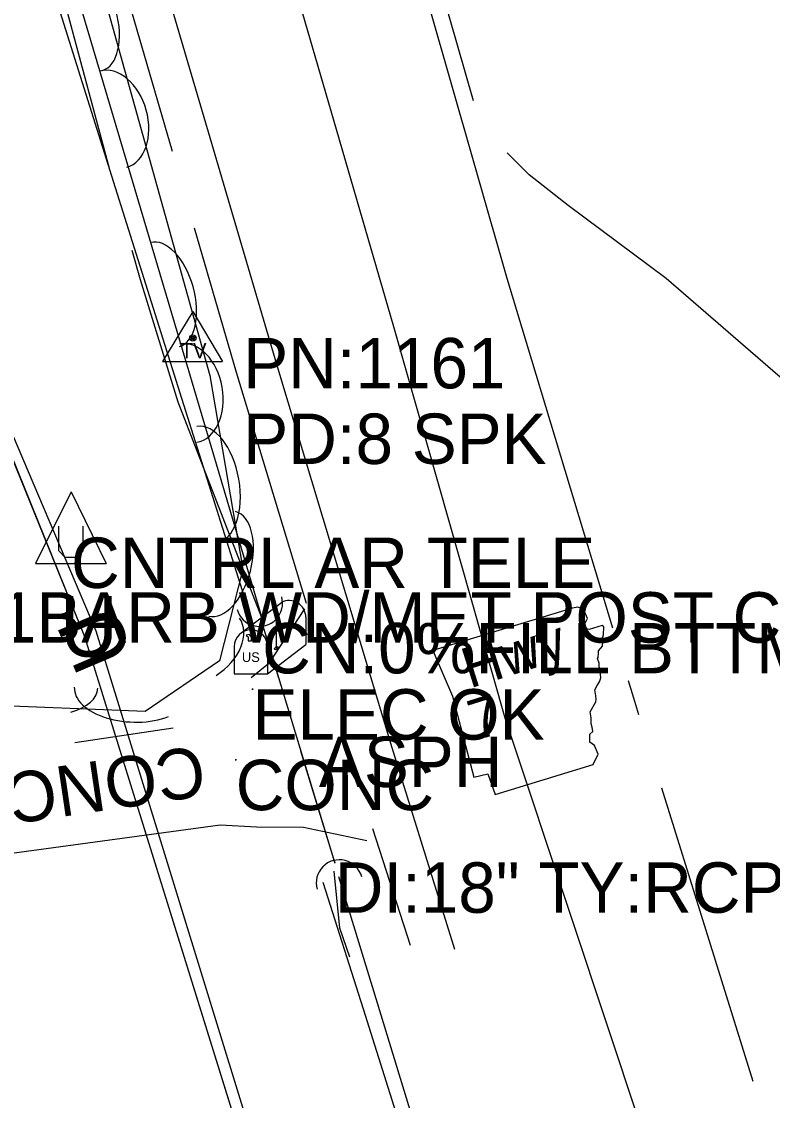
# Model space of a CAD drawing. Extents: x 954793 to 988390, y 1867850 to 1924428.
# Drawn here: x 960863.5 to 960938.1, y 1908205.7 to 1908312.7 of the extents above; entities that cross this region are included whole.
import ezdxf

# ---------------------------------------------------------------- set-up
doc = ezdxf.new("R2010")
doc.units = 0
for name, color, linetype in [('Default', 7, 'Continuous'), ('S_CROSS_DRAIN', 7, 'Continuous'), ('S_DITCHLINE', 7, 'Continuous'), ('S_DRG_PT_SYM', 7, 'Continuous'), ('S_DRIVEWAY', 7, 'Continuous'), ('S_DRIVEWAY_ANNOT', 7, 'Continuous'), ('S_EDGE_PAVEMENT', 7, 'Continuous'), ('S_FIBER_OPTIC_CABLE', 7, 'Continuous'), ('S_GRAVEL_ROAD', 7, 'Continuous'), ('S_HWY_SYMBOLS', 7, 'Continuous'), ('S_MAILBOX', 7, 'Continuous'), ('S_MSC_PT_SYM', 7, 'Continuous'), ('S_PAVEMENT_CROWN', 7, 'Continuous'), ('S_SECONDARY_CTL', 7, 'Continuous'), ('S_SECONDARY_CTL_ANNOT', 7, 'Continuous'), ('S_SHOULDER', 7, 'Continuous'), ('S_SIDE_DRAIN', 7, 'Continuous'), ('S_SIDE_DRAIN_ANNOT', 7, 'Continuous'), ('S_STREAM', 7, 'Continuous'), ('S_SURVEY_TEXT_ANNOT', 7, 'Continuous'), ('S_TREE', 7, 'Continuous'), ('S_UNDERGROUND_CABLE', 7, 'Continuous'), ('S_UTILITY_POLE_ANNOT', 7, 'Continuous'), ('S_UTL_PT_SYM', 7, 'Continuous')]:
    doc.layers.add(name, color=color, linetype=linetype)

msp = doc.modelspace()

# ---------------------------------------------------------------- linework, layer by layer
at = {"layer": 'S_CROSS_DRAIN'}
for centre, start, end in [((960887.14, 1908255.03), 195.5364, 15.8656), ((960895.08, 1908227.28), 15.5364, 195.8656)]:
    msp.add_arc(centre, 2.3, start, end, dxfattribs=at)
at = {"layer": 'S_DITCHLINE'}
for points in [[(960887.32, 1908253.86), (960880.93, 1908275.39), (960874.54, 1908296.92), (960868.15, 1908318.45), (960861.75, 1908339.98), (960857.4, 1908356.82), (960853.05, 1908373.67), (960848.7, 1908390.51), (960844.35, 1908407.36), (960839.66, 1908426.7), (960834.97, 1908446.05), (960830.28, 1908465.39), (960825.59, 1908484.73), (960820.79, 1908504.11), (960815.99, 1908523.48), (960811.19, 1908542.85), (960806.38, 1908562.22)], [(960886.41, 1908253.21), (960879.64, 1908274.72), (960872.87, 1908296.22), (960866.11, 1908317.73), (960859.34, 1908339.24), (960855.61, 1908355.76), (960851.88, 1908372.29), (960848.14, 1908388.81), (960844.41, 1908405.34), (960839.36, 1908425.07), (960834.31, 1908444.81), (960829.25, 1908464.54), (960824.2, 1908484.28), (960819.45, 1908503.76), (960814.7, 1908523.23), (960809.95, 1908542.71), (960805.2, 1908562.19)], [(960909.41, 1908177), (960905.43, 1908189.59), (960901.44, 1908202.17), (960897.46, 1908214.75), (960893.47, 1908227.34)], [(960910.38, 1908177.7), (960906.54, 1908190.25), (960902.7, 1908202.8), (960898.86, 1908215.34), (960895.02, 1908227.89)]]:
    msp.add_lwpolyline(points, dxfattribs=at)
at = {"layer": 'S_DRG_PT_SYM'}
for points in [[(960887.41, 1908253.07), (960887.36, 1908253.05), (960887.41, 1908253.07), (960887.42, 1908253.02), (960887.41, 1908253.07), (960887.45, 1908253.08), (960887.41, 1908253.07), (960887.39, 1908253.12)], [(960887.41, 1908253.07), (960887.36, 1908253.05), (960887.41, 1908253.07), (960887.42, 1908253.02), (960887.41, 1908253.07), (960887.45, 1908253.08), (960887.41, 1908253.07), (960887.39, 1908253.12)], [(960894.62, 1908229.32), (960894.57, 1908229.31), (960894.62, 1908229.32), (960894.63, 1908229.28), (960894.62, 1908229.32), (960894.66, 1908229.34), (960894.62, 1908229.32), (960894.6, 1908229.37)], [(960894.62, 1908229.32), (960894.57, 1908229.31), (960894.62, 1908229.32), (960894.63, 1908229.28), (960894.62, 1908229.32), (960894.66, 1908229.34), (960894.62, 1908229.32), (960894.6, 1908229.37)]]:
    msp.add_lwpolyline(points, close=True, dxfattribs=at)
for points in [[(960887.41, 1908253.07), (960887.41, 1908253.12), (960887.41, 1908253.07), (960887.36, 1908253.07), (960887.41, 1908253.07), (960887.41, 1908253.02), (960887.41, 1908253.07), (960887.46, 1908253.07)], [(960894.62, 1908229.32), (960894.62, 1908229.37), (960894.62, 1908229.32), (960894.57, 1908229.32), (960894.62, 1908229.32), (960894.62, 1908229.27), (960894.62, 1908229.32), (960894.67, 1908229.32)]]:
    msp.add_lwpolyline(points, dxfattribs=at)
at = {"layer": 'S_DRIVEWAY'}
for points in [[(960891.63, 1908254.46), (960888.04, 1908249.01), (960886.32, 1908247.64)], [(960878.58, 1908242.65), (960868.84, 1908241.18)], [(960835.9, 1908227.05), (960844.09, 1908228), (960858.41, 1908229.67), (960870.84, 1908231.37), (960883.26, 1908233.06), (960886.86, 1908232.86), (960891.51, 1908232.83), (960897.8, 1908231.49)]]:
    msp.add_lwpolyline(points, dxfattribs=at)
at = {"layer": 'S_EDGE_PAVEMENT'}
for points in [[(960922.21, 1908252.54), (960918.02, 1908266.43), (960911.74, 1908287.24), (960905.85, 1908307.8), (960899.95, 1908328.37)], [(960906.54, 1908220.67), (960900.33, 1908240.69), (960894.59, 1908259.7), (960888.86, 1908278.72), (960882.58, 1908300.08), (960876.3, 1908321.43)], [(960924.81, 1908243.97), (960924.3, 1908245.62), (960923.78, 1908247.34)], [(960936.15, 1908207.57), (960930.39, 1908226.07), (960927.09, 1908236.67)]]:
    msp.add_lwpolyline(points, dxfattribs=at)
at = {"layer": 'S_FIBER_OPTIC_CABLE'}
for p, q in [((960869.82, 1908251.7), (960854.87, 1908288.42)), ((960891.98, 1908180.4), (960869.82, 1908251.7))]:
    msp.add_line(p, q, dxfattribs=at)
msp.add_lwpolyline([(961081.83, 1907606.88), (961053.28, 1907681.02), (961044.49, 1907703.08), (961020.93, 1907758.22), (961005.92, 1907782.73), (960987.1, 1907843.87), (960969.61, 1907900.06), (960943.98, 1907978.41), (960937.29, 1908004.83), (960935.36, 1908054.81), (960930.43, 1908064.73), (960909.05, 1908124.58), (960891.98, 1908180.4), (960869.82, 1908251.7), (960854.87, 1908288.42), (960823.74, 1908306.68), (960802.22, 1908384.11)], dxfattribs=at)
msp.add_lwpolyline([(961081.83, 1907606.88), (961053.28, 1907681.02), (961044.49, 1907703.08), (961020.93, 1907758.22), (961005.92, 1907782.73), (960987.1, 1907843.87), (960969.61, 1907900.06), (960943.98, 1907978.41), (960937.29, 1908004.83), (960935.36, 1908054.81), (960930.43, 1908064.73), (960909.05, 1908124.58), (960891.98, 1908180.4), (960869.82, 1908251.7), (960854.87, 1908288.42), (960823.74, 1908306.68), (960802.22, 1908384.11)], dxfattribs=at)
at = {"layer": 'S_GRAVEL_ROAD'}
msp.add_lwpolyline([(960945.48, 1908271.75), (960943.26, 1908273.63), (960927.51, 1908287.25), (960917.77, 1908294.48), (960913.93, 1908297.52), (960911.72, 1908299.69)], dxfattribs=at)
at = {"layer": 'S_HWY_SYMBOLS'}
msp.add_lwpolyline([(960904.37, 1908250.34), (960906.31, 1908245.82), (960908.41, 1908237.76), (960909.81, 1908238.12), (960910.55, 1908236.04), (960920.28, 1908239.02), (960920.75, 1908240.06), (960920.39, 1908240.92), (960919.94, 1908241.23), (960919.95, 1908242.03), (960920.23, 1908242.29), (960920.18, 1908242.72), (960920.08, 1908243.05), (960920.06, 1908243.66), (960919.96, 1908244.26), (960920.54, 1908245.24), (960920.55, 1908245.51), (960920.52, 1908245.85), (960920.43, 1908246.45), (960920.65, 1908246.87), (960920.9, 1908247.22), (960921.04, 1908247.62), (960921.01, 1908247.97), (960920.97, 1908248.39), (960920.87, 1908248.72), (960920.85, 1908249.07), (960920.69, 1908249.55), (960920.75, 1908249.66), (960920.78, 1908250.11), (960920.81, 1908250.3), (960921.19, 1908250.78), (960921.23, 1908251.23), (960921.15, 1908251.48), (960921.29, 1908251.88), (960921.31, 1908252.68), (960921.17, 1908252.82), (960919.88, 1908252.41), (960919.59, 1908252.49), (960919.38, 1908252.87), (960919.54, 1908253.19), (960919.71, 1908253.51), (960919.4, 1908254.21), (960919.03, 1908254.54), (960918.74, 1908254.63), (960918.22, 1908254.55), (960904.37, 1908250.34)], dxfattribs=at)
at = {"layer": 'S_MAILBOX'}
for p, q in [((960885.19, 1908252), (960889.32, 1908255.11)), ((960888.81, 1908253.29), (960888.81, 1908250.57)), ((960891.76, 1908253.63), (960891.76, 1908250.92)), ((960887.96, 1908248.01), (960891.76, 1908250.92)), ((960884.64, 1908250.72), (960884.64, 1908248.01)), ((960887.96, 1908250.72), (960887.96, 1908248.01)), ((960884.64, 1908248.01), (960887.96, 1908248.01))]:
    msp.add_line(p, q, dxfattribs=at)
for points in [[(960888.81, 1908253.29), (960889.91, 1908252.62), (960888.81, 1908252.28)], [(960885.82, 1908251.84), (960886.04, 1908251.7), (960886.04, 1908251.31), (960886.35, 1908251.31), (960886.35, 1908251.67), (960886.15, 1908251.92), (960885.82, 1908251.87)]]:
    msp.add_lwpolyline(points, dxfattribs=at)
for centre, end in [((960890.09, 1908253.63), 117.5718), ((960886.3, 1908250.72), 180)]:
    msp.add_arc(centre, 1.66, 0, end, dxfattribs=at)
msp.add_ellipse((960888.81, 1908250.57), major_axis=(0.145, 0.132), ratio=0.564646, dxfattribs=at)
at = {"layer": 'S_MSC_PT_SYM'}
for points in [[(960886.46, 1908246.5), (960886.46, 1908246.55), (960886.46, 1908246.5), (960886.41, 1908246.5), (960886.46, 1908246.5), (960886.46, 1908246.45), (960886.46, 1908246.5), (960886.51, 1908246.5)], [(960886.46, 1908246.5), (960886.46, 1908246.55), (960886.46, 1908246.5), (960886.41, 1908246.5), (960886.46, 1908246.5), (960886.46, 1908246.45), (960886.46, 1908246.5), (960886.51, 1908246.5)], [(960893.05, 1908241.8), (960893.05, 1908241.85), (960893.05, 1908241.8), (960893, 1908241.8), (960893.05, 1908241.8), (960893.05, 1908241.75), (960893.05, 1908241.8), (960893.1, 1908241.8)], [(960893.05, 1908241.8), (960893.05, 1908241.85), (960893.05, 1908241.8), (960893, 1908241.8), (960893.05, 1908241.8), (960893.05, 1908241.75), (960893.05, 1908241.8), (960893.1, 1908241.8)], [(960884.79, 1908239.5), (960884.79, 1908239.55), (960884.79, 1908239.5), (960884.74, 1908239.5), (960884.79, 1908239.5), (960884.79, 1908239.45), (960884.79, 1908239.5), (960884.84, 1908239.5)], [(960884.79, 1908239.5), (960884.79, 1908239.55), (960884.79, 1908239.5), (960884.74, 1908239.5), (960884.79, 1908239.5), (960884.79, 1908239.45), (960884.79, 1908239.5), (960884.84, 1908239.5)]]:
    msp.add_lwpolyline(points, close=True, dxfattribs=at)
for points in [[(960886.46, 1908246.5), (960886.46, 1908246.55), (960886.46, 1908246.5), (960886.41, 1908246.5), (960886.46, 1908246.5), (960886.46, 1908246.45), (960886.46, 1908246.5), (960886.51, 1908246.5)], [(960893.05, 1908241.8), (960893.05, 1908241.85), (960893.05, 1908241.8), (960893, 1908241.8), (960893.05, 1908241.8), (960893.05, 1908241.75), (960893.05, 1908241.8), (960893.1, 1908241.8)], [(960884.79, 1908239.5), (960884.79, 1908239.55), (960884.79, 1908239.5), (960884.74, 1908239.5), (960884.79, 1908239.5), (960884.79, 1908239.45), (960884.79, 1908239.5), (960884.84, 1908239.5)]]:
    msp.add_lwpolyline(points, dxfattribs=at)
at = {"layer": 'S_PAVEMENT_CROWN'}
msp.add_lwpolyline([(960965.52, 1908078.27), (960958.29, 1908100.22), (960951.05, 1908122.17), (960945.06, 1908140.77), (960939.07, 1908159.37), (960932.01, 1908181.32), (960924.95, 1908203.26), (960918.24, 1908223.44), (960911.54, 1908243.63), (960906.02, 1908263.03), (960900.5, 1908282.44), (960894.26, 1908303.84), (960888.03, 1908325.24)], dxfattribs=at)
at = {"layer": 'S_SECONDARY_CTL'}
for p, q in [((960880.54, 1908283.95), (960877.53, 1908279)), ((960880.54, 1908283.95), (960883.49, 1908279)), ((960877.53, 1908279), (960883.49, 1908279))]:
    msp.add_line(p, q, dxfattribs=at)
for radius in [0.311, 0.183, 0.103]:
    msp.add_circle((960880.54, 1908281.34), radius, dxfattribs=at)
at = {"layer": 'S_SHOULDER'}
for points in [[(960878.52, 1908299.82), (960872.51, 1908320.55), (960866.76, 1908342.01), (960861.02, 1908363.47), (960855.97, 1908382.82), (960850.93, 1908402.16), (960846.37, 1908419.96), (960841.81, 1908437.76), (960836.11, 1908461.04), (960830.42, 1908484.32), (960825.7, 1908503.57), (960820.99, 1908522.82), (960816.11, 1908543.02), (960811.24, 1908563.23), (960806.61, 1908582.38), (960801.98, 1908601.53), (960796.71, 1908623.15), (960791.44, 1908644.76), (960786.96, 1908662.91), (960782.48, 1908681.05), (960777.34, 1908701.64), (960772.2, 1908722.22)], [(960908.38, 1908304.85), (960905.28, 1908315.69)], [(960891.83, 1908255), (960884.86, 1908277.92), (960880.71, 1908292.24)], [(960902.13, 1908221.08), (960898.39, 1908232.65)]]:
    msp.add_lwpolyline(points, dxfattribs=at)
at = {"layer": 'S_SIDE_DRAIN'}
for p, q in [((960889.07, 1908247.58), (960887.41, 1908253.07)), ((960894.62, 1908229.32), (960891.27, 1908240.35))]:
    msp.add_line(p, q, dxfattribs=at)
msp.add_lwpolyline([(960894.62, 1908229.32), (960887.41, 1908253.07)], dxfattribs=at)
msp.add_lwpolyline([(960894.62, 1908229.32), (960887.41, 1908253.07)], dxfattribs=at)
at = {"layer": 'S_STREAM'}
for points in [[(960872.29, 1908298.02), (960872.25, 1908298.16), (960865.14, 1908324.64), (960847.95, 1908389.51), (960838.57, 1908427.95), (960818.74, 1908507.87), (960805.7, 1908562.56)], [(960887.37, 1908253.59), (960879.08, 1908274.98), (960875.33, 1908287.12), (960874.52, 1908290.01)], [(960896.11, 1908219.93), (960895.14, 1908222.81), (960894.56, 1908228.44)]]:
    msp.add_lwpolyline(points, dxfattribs=at)
at = {"layer": 'S_TREE'}
msp.add_lwpolyline([(960838.71, 1908433.29), (960882.22, 1908277.62), (960885.51, 1908258.41), (960883.18, 1908249.31), (960875.81, 1908244.29), (960859.21, 1908244.94), (960832.28, 1908249.71), (960808.35, 1908250.18), (960791.6, 1908248.82), (960787.28, 1908243.35), (960784.76, 1908240.67), (960769.45, 1908241.09), (960767.4, 1908246.66), (960765.37, 1908249.96), (960758.28, 1908252.45), (960754.58, 1908250.99), (960749.55, 1908245.77), (960746.48, 1908238.65), (960738.27, 1908237.81), (960721.64, 1908238.59), (960709.83, 1908240.37), (960698.17, 1908241.29), (960690.71, 1908240.89)], dxfattribs=at)
for centre, major_axis, ratio, start_param, end_param in [((960870.12, 1908313.03), (-1.44, 5.15), 0.540699, 3.141593, 6.283185), ((960872.64, 1908303.04), (-1.33, 4.77), 0.685311, 3.141593, 6.283185), ((960877.77, 1908285.65), (-1.44, 5.15), 0.540699, 3.141593, 6.283185), ((960880.1, 1908275.87), (-0.84, 4.88), 0.685311, 3.141593, 6.283185), ((960881.92, 1908266.78), (-0.99, 5.78), 0.55008, 3.141593, 6.283185), ((960883.45, 1908258.93), (1.33, 5.18), 0.540699, 3.141593, 6.283185), ((960881.08, 1908250.76), (4.1, 2.79), 0.685311, 4.678315, 6.283185), ((960865.77, 1908246.81), (5.34, -0.21), 0.540699, 5.255681, 6.283185), ((960874.63, 1908246.46), (5.86, -0.23), 0.55008, 3.141593, 5.373756)]:
    msp.add_ellipse(centre, major_axis=major_axis, ratio=ratio, start_param=start_param, end_param=end_param, dxfattribs=at)
at = {"layer": 'S_UNDERGROUND_CABLE'}
for p, q in [((960870.95, 1908252.27), (960855.38, 1908288.78)), ((960868.45, 1908266.07), (960864.93, 1908258.98)), ((960868.45, 1908266.07), (960871.94, 1908258.98)), ((960867.25, 1908260.22), (960867.25, 1908262.66)), ((960869.62, 1908262.66), (960869.62, 1908260.22)), ((960867.87, 1908259.56), (960867.25, 1908260.22)), ((960869.07, 1908259.56), (960867.87, 1908259.56)), ((960869.62, 1908260.22), (960869.07, 1908259.56)), ((960864.93, 1908258.98), (960871.94, 1908258.98)), ((960893, 1908180.71), (960870.95, 1908252.27))]:
    msp.add_line(p, q, dxfattribs=at)
msp.add_lwpolyline([(960924.47, 1908058.47), (960931.11, 1908064.94), (960909.84, 1908124.82), (960893, 1908180.71), (960870.95, 1908252.27), (960855.38, 1908288.78), (960824.66, 1908307.36), (960801.48, 1908384.93), (960790.3, 1908429.37), (960771.93, 1908510.1), (960754.11, 1908582.75), (960734.09, 1908667.42), (960716.61, 1908744.97), (960698.42, 1908828.21), (960681.52, 1908913.94), (960663.18, 1908993.44), (960645.91, 1909068.19), (960624.8, 1909158.96), (960612.33, 1909198.29), (960609.74, 1909220.21), (960585.48, 1909279.43), (960521.44, 1909367.02), (960488.5, 1909420.49)], dxfattribs=at)
msp.add_lwpolyline([(960924.47, 1908058.47), (960931.11, 1908064.94), (960909.84, 1908124.82), (960893, 1908180.71), (960870.95, 1908252.27), (960855.38, 1908288.78), (960824.66, 1908307.36), (960801.48, 1908384.93), (960790.3, 1908429.37), (960771.93, 1908510.1), (960754.11, 1908582.75), (960734.09, 1908667.42), (960716.61, 1908744.97), (960698.42, 1908828.21), (960681.52, 1908913.94), (960663.18, 1908993.44), (960645.91, 1909068.19), (960624.8, 1909158.96), (960612.33, 1909198.29), (960609.74, 1909220.21), (960585.48, 1909279.43), (960521.44, 1909367.02), (960488.5, 1909420.49)], dxfattribs=at)
at = {"layer": 'S_UTL_PT_SYM'}
msp.add_lwpolyline([(960869.82, 1908251.7), (960869.82, 1908251.75), (960869.82, 1908251.7), (960869.77, 1908251.7), (960869.82, 1908251.7), (960869.82, 1908251.65), (960869.82, 1908251.7), (960869.87, 1908251.7)], dxfattribs=at)
msp.add_lwpolyline([(960869.82, 1908251.7), (960869.77, 1908251.68), (960869.82, 1908251.7), (960869.84, 1908251.65), (960869.82, 1908251.7), (960869.87, 1908251.72), (960869.82, 1908251.7), (960869.8, 1908251.74)], close=True, dxfattribs=at)
msp.add_lwpolyline([(960869.82, 1908251.7), (960869.77, 1908251.68), (960869.82, 1908251.7), (960869.84, 1908251.65), (960869.82, 1908251.7), (960869.87, 1908251.72), (960869.82, 1908251.7), (960869.8, 1908251.74)], close=True, dxfattribs=at)

# ---------------------------------------------------------------- texts
at = {"layer": 'Default'}
for rotation, p in [(360, (960867.32, 1908249.73)), (113.0956, (960874.71, 1908249.93))]:
    msp.add_text('U', height=6, rotation=rotation, dxfattribs=at).set_placement(p)
at = {"layer": 'S_DRIVEWAY_ANNOT'}
msp.add_text('CONCRETE DRIVE', height=5.0004, rotation=188.4013, dxfattribs=at).set_placement((960881.34, 1908240.93))
at = {"layer": 'S_HWY_SYMBOLS'}
for s, p in [('Hwy', (960908.02, 1908246.56)), ('7', (960908.66, 1908241.39))]:
    msp.add_text(s, height=4, rotation=17.5104, dxfattribs=at).set_placement(p)
at = {"layer": 'S_MAILBOX'}
msp.add_text('US', height=0.96, rotation=360, dxfattribs=at).set_placement((960885.4, 1908249.2))
at = {"layer": 'S_SECONDARY_CTL'}
msp.add_text('TV', height=1.5, rotation=360, dxfattribs=at).set_placement((960879.33, 1908279.33))
at = {"layer": 'S_SECONDARY_CTL_ANNOT'}
for s, p in [('PN:1161', (960885.54, 1908276.34)), ('PD:8 SPK', (960885.54, 1908268.84))]:
    msp.add_text(s, height=5, dxfattribs=at).set_placement(p)
at = {"layer": 'S_SIDE_DRAIN_ANNOT'}
for s, p in [('CN:0%FILL BTTM OF PIPE', (960887.41, 1908248.07)), ('DI:18" TY:RCP CN:0%FILL BTTM OF', (960894.62, 1908224.32))]:
    msp.add_text(s, height=5, dxfattribs=at).set_placement(p)
at = {"layer": 'S_SURVEY_TEXT_ANNOT'}
for s, p in [('5.0 FE 1BARB WD/MET POST CN:GOO', (960839.74, 1908251.12)), ('ELEC OK', (960886.46, 1908241.5)), ('ASPH', (960893.05, 1908236.8)), ('CONC', (960884.79, 1908234.5))]:
    msp.add_text(s, height=5, dxfattribs=at).set_placement(p)
at = {"layer": 'S_UTILITY_POLE_ANNOT'}
msp.add_text('CNTRL AR TELE', height=5, dxfattribs=at).set_placement((960868.45, 1908256.54))

doc.saveas('drawing.dxf')
